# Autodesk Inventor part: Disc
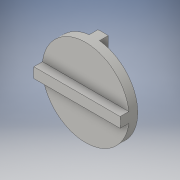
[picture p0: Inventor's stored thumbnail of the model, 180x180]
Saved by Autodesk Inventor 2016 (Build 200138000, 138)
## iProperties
Created: 2020-03
Part Number: Disc
Material: Generic
Document SubType Name: Modeling
Designer: Furqan
Density: 1 g/cm^3
Appearance: Default
Author: Furqan
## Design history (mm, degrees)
sketch "Sketch1"
  geometry: C1 r 50.8 at (0, 0); 1 further point
  constraints: 1 centre point, 1 coincident
  dimensions: "d0" = 101.6 diameter of C1
extrude "Extrusion1" new body sketch "Sketch1" distance "d1" = 10.16; taper "d2" = 0 deg
sketch "Sketch2"
  geometry: L1 (-50.445, 5.994)-(50.445, 5.994); L2 (-50.445, -5.994)-(50.445, -5.994); A1 r 50.8 centre (0, 0) between (-50.445, 5.994) and (50.445, 5.994) reference; 1 further point
  constraints: 4 end point, 4 point on circle, 2 horizontal, 1 parallel
  dimensions: "d3" = 11.9888 distance between parallel lines of L1 L2
extrude "Extrusion2" join sketch "Sketch2" distance "d4" = 10.16; taper "d5" = 0 deg
sketch "Sketch4"
  geometry: L1 (-5.994, 50.445)-(-5.994, -50.445); L2 (5.994, 50.445)-(5.994, -50.445); A1 r 50.8 centre (0, 0) between (-5.994, 50.445) and (-5.994, -50.445) reference; 1 further point
  constraints: 4 end point, 4 point on circle, 2 vertical, 1 parallel
  dimensions: "d6" = 11.9888 distance between parallel lines of L2 L1
extrude "Extrusion3" join sketch "Sketch4" distance "d7" = 10.16; taper "d8" = 0 deg
body "Solid1"
